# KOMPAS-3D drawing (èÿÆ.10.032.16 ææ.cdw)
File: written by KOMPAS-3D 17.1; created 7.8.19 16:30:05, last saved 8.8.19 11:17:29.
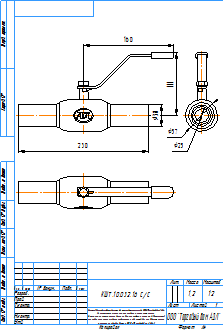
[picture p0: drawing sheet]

Sheet 1: A4, portrait

Title block, sheet 1: name: КШТ.10.032.16 С/С; material: Сталь 20  ГОСТ 1050-2013; mass: 1,2; sheets: 1; sheet format: A4; stored path: C:\Users\kka\KOMPAS_Work\Модели кранов для исследований\DN65\КШТ.10.065.16 СС.cdw

Views: Вид 1, Проекционный вид 2, Проекционный вид 3
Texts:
  kka
  adl
  Рама для чертежей
  Лит-Масса-Масштаб
  Материал-Предприятие
  Масштаб
  Изм.
  Лист
  № докум.
  Подп.
  Дата
  Лит.
  Разраб.
  Пров.
  Т.контр.
  Листов
  Внимание! Данный продукт является объектом авторского права ООО «Торговый Дом АДЛ».
  Запрещается изменение, копирование, распространение
  (в том числе путем копирования на другие сайты и ресурсы в Интернете)
  или любое иное использование информации и объектов без предварительного
  согласия правообладателя (ООО «Торговый Дом АДЛ»).
  Н.контр.
  Утв.
  ООО "Торговый дом АДЛ"
  Изменение
  Номер документа
  Подпись
  Обозначение документа
  Наименование изделия
  Масса изделия по ГОСТ 2.109-73
  Порядковый номер листа
  Общее количество листов в документе
  Характер работы, выполненной лицом, подписавшим документ
  Наименование или индекс предприятия, выпускающего документ
  Инв. № подл.
  Подп. и дата
  Взам. инв. №
  Инв. № дубл.
  Инвентарный номер подлинника по ГОСТ 2.501-68
  Подпись принявшего подлинник в отдел технической документации
  Инвентарный номер подлинника, взамен которого выпущен данный подлинник
  Инвентарный номер дубликата по ГОСТ 2.502-68
  Подпись принявшего дубликат в отдел технической документации
  Справ. №
  Перв. примен.
  Обозначение документа, взамен или на основании которого выпущен данный документ
  Обозначение документа, в котором впервые записан данный документ
  Подпись лица, копировавшего чертеж
  Обозначение формата листа
  !Рама для чертежа
Dimensions and other numbers on the sheet: 230; 111; 160; 38; 57; 25; 1:2; 1; 1,2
